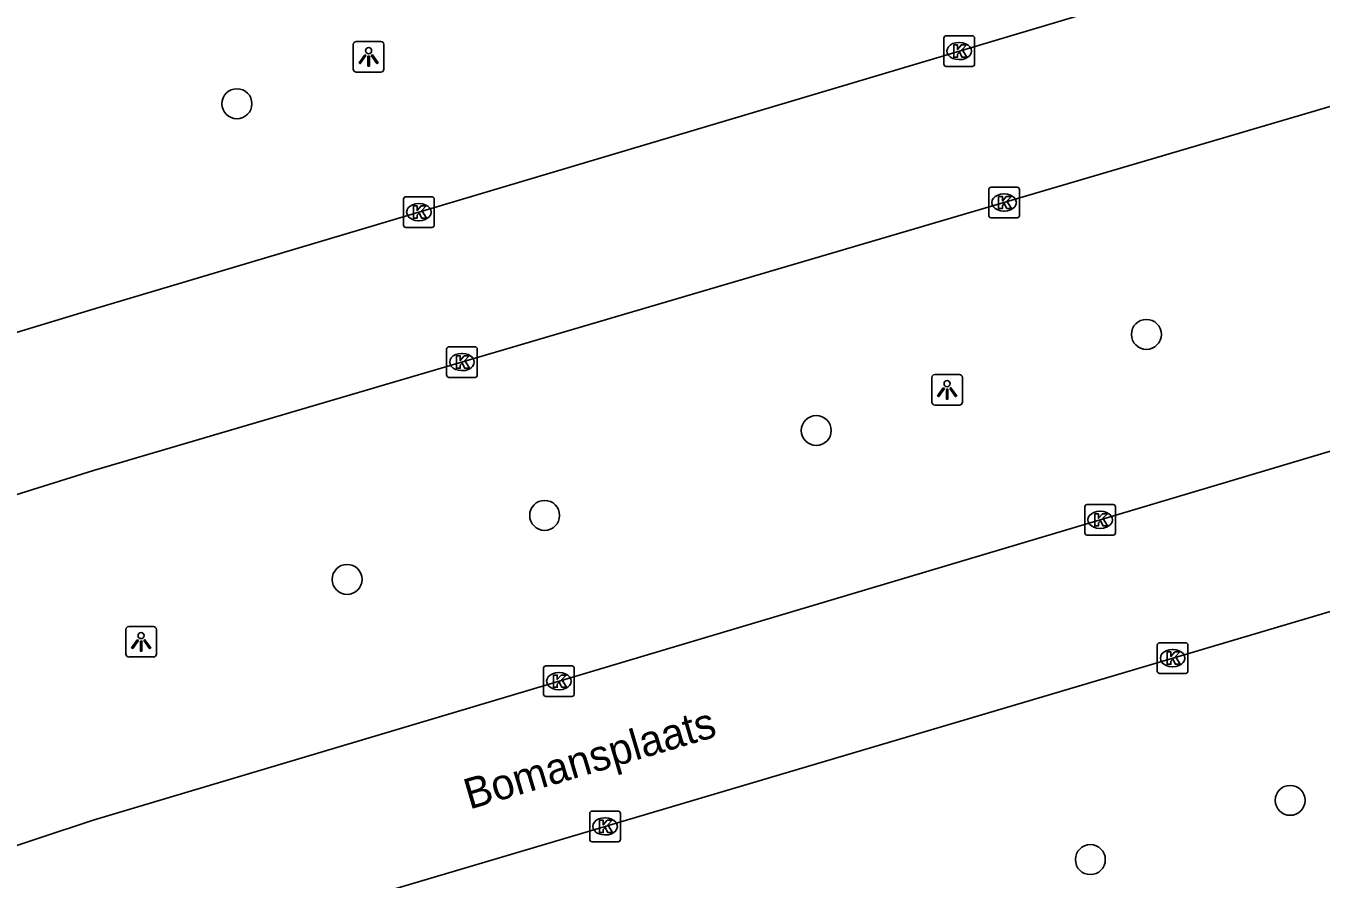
# Model space of a CAD drawing. Extents: x 161354 to 161876, y 382161 to 382804.
# Drawn here: x 161747.93 to 161790.23, y 382382.57 to 382410.43 of the extents above; entities that cross this region are included whole.
import ezdxf

# ---------------------------------------------------------------- set-up
doc = ezdxf.new("R2010")
doc.units = 0
for name, color, linetype in [('IMGEO_Boom', 7, 'Continuous'), ('IMGEO_Kolk', 7, 'Continuous'), ('IMGEO_Lichtpunt', 7, 'Continuous'), ('IMGEO_Openbare_ruimte_label', 7, 'Continuous'), ('IMGEO_Rijbaan_lokaal_open', 7, 'Continuous')]:
    doc.layers.add(name, color=color, linetype=linetype)

msp = doc.modelspace()

# ---------------------------------------------------------------- linework, layer by layer
at = {"layer": 'IMGEO_Boom'}
for centre in [(161754.825, 382407.891), (161784.522, 382400.359), (161773.743, 382397.219), (161764.873, 382394.448), (161758.423, 382392.358), (161789.216, 382385.143), (161782.692, 382383.207)]:
    msp.add_circle(centre, 0.489, dxfattribs=at)
at = {"layer": 'IMGEO_Kolk'}
for p, q in [((161777.909, 382409.184), (161777.909, 382410.036)), ((161777.984, 382410.11), (161778.836, 382410.11)), ((161778.397, 382409.89), (161778.422, 382409.89)), ((161778.91, 382410.036), (161778.91, 382409.184)), ((161778.836, 382409.11), (161777.984, 382409.11)), ((161778.42, 382409.33), (161778.395, 382409.33)), ((161779.449, 382405.164), (161780.301, 382405.164)), ((161760.266, 382403.925), (161760.266, 382404.777)), ((161760.341, 382404.851), (161761.193, 382404.851)), ((161761.267, 382404.777), (161761.267, 382403.925)), ((161779.374, 382404.238), (161779.374, 382405.09)), ((161779.862, 382404.944), (161779.887, 382404.944)), ((161780.375, 382405.09), (161780.375, 382404.238)), ((161760.754, 382404.631), (161760.779, 382404.631)), ((161779.885, 382404.384), (161779.86, 382404.384)), ((161760.777, 382404.071), (161760.752, 382404.071)), ((161780.301, 382404.164), (161779.449, 382404.164)), ((161761.193, 382403.851), (161760.341, 382403.851)), ((161761.673, 382399.029), (161761.673, 382399.881)), ((161761.748, 382399.955), (161762.6, 382399.955)), ((161762.161, 382399.735), (161762.186, 382399.735)), ((161762.674, 382399.881), (161762.674, 382399.029)), ((161762.6, 382398.955), (161761.748, 382398.955)), ((161762.184, 382399.175), (161762.159, 382399.175)), ((161782.512, 382393.877), (161782.512, 382394.729)), ((161782.587, 382394.803), (161783.439, 382394.803)), ((161783, 382394.583), (161783.025, 382394.583)), ((161783.513, 382394.729), (161783.513, 382393.877)), ((161783.439, 382393.803), (161782.587, 382393.803)), ((161783.023, 382394.023), (161782.998, 382394.023)), ((161784.878, 382389.361), (161784.878, 382390.213)), ((161784.953, 382390.287), (161785.805, 382390.287)), ((161785.366, 382390.067), (161785.391, 382390.067)), ((161785.879, 382390.213), (161785.879, 382389.361)), ((161764.914, 382389.535), (161765.766, 382389.535)), ((161785.389, 382389.507), (161785.364, 382389.507)), ((161764.839, 382388.609), (161764.839, 382389.461)), ((161765.327, 382389.315), (161765.352, 382389.315)), ((161765.84, 382389.461), (161765.84, 382388.609)), ((161785.805, 382389.287), (161784.953, 382389.287)), ((161765.35, 382388.755), (161765.325, 382388.755)), ((161765.766, 382388.535), (161764.914, 382388.535)), ((161766.345, 382383.866), (161766.345, 382384.718)), ((161766.42, 382384.792), (161767.272, 382384.792)), ((161766.833, 382384.572), (161766.858, 382384.572)), ((161767.346, 382384.718), (161767.346, 382383.866)), ((161766.856, 382384.012), (161766.831, 382384.012)), ((161767.272, 382383.792), (161766.42, 382383.792))]:
    msp.add_line(p, q, dxfattribs=at)
for points in [[(161777.909, 382409.184), (161777.909, 382410.036)], [(161777.984, 382410.11), (161778.836, 382410.11)], [(161778.23, 382409.81), (161778.353, 382409.81), (161778.353, 382409.659), (161778.483, 382409.81), (161778.647, 382409.81), (161778.501, 382409.659), (161778.654, 382409.41), (161778.502, 382409.41), (161778.417, 382409.574), (161778.353, 382409.507), (161778.353, 382409.41), (161778.23, 382409.41), (161778.23, 382409.81)], [(161778.91, 382410.036), (161778.91, 382409.184)], [(161778.836, 382409.11), (161777.984, 382409.11)], [(161779.449, 382405.164), (161780.301, 382405.164)], [(161760.266, 382403.925), (161760.266, 382404.777)], [(161760.341, 382404.851), (161761.193, 382404.851)], [(161761.267, 382404.777), (161761.267, 382403.925)], [(161779.374, 382404.238), (161779.374, 382405.09)], [(161779.695, 382404.864), (161779.818, 382404.864), (161779.818, 382404.713), (161779.948, 382404.864), (161780.112, 382404.864), (161779.966, 382404.713), (161780.119, 382404.464), (161779.967, 382404.464), (161779.882, 382404.628), (161779.818, 382404.561), (161779.818, 382404.464), (161779.695, 382404.464), (161779.695, 382404.864)], [(161780.375, 382405.09), (161780.375, 382404.238)], [(161760.587, 382404.551), (161760.71, 382404.551), (161760.71, 382404.4), (161760.84, 382404.551), (161761.004, 382404.551), (161760.858, 382404.4), (161761.011, 382404.151), (161760.859, 382404.151), (161760.774, 382404.315), (161760.71, 382404.248), (161760.71, 382404.151), (161760.587, 382404.151), (161760.587, 382404.551)], [(161780.301, 382404.164), (161779.449, 382404.164)], [(161761.193, 382403.851), (161760.341, 382403.851)], [(161761.673, 382399.029), (161761.673, 382399.881)], [(161761.748, 382399.955), (161762.6, 382399.955)], [(161761.994, 382399.655), (161762.117, 382399.655), (161762.117, 382399.504), (161762.247, 382399.655), (161762.411, 382399.655), (161762.265, 382399.504), (161762.418, 382399.255), (161762.266, 382399.255), (161762.181, 382399.419), (161762.117, 382399.352), (161762.117, 382399.255), (161761.994, 382399.255), (161761.994, 382399.655)], [(161762.674, 382399.881), (161762.674, 382399.029)], [(161762.6, 382398.955), (161761.748, 382398.955)], [(161782.512, 382393.877), (161782.512, 382394.729)], [(161782.587, 382394.803), (161783.439, 382394.803)], [(161783.513, 382394.729), (161783.513, 382393.877)], [(161782.833, 382394.503), (161782.956, 382394.503), (161782.956, 382394.352), (161783.086, 382394.503), (161783.25, 382394.503), (161783.104, 382394.352), (161783.257, 382394.103), (161783.105, 382394.103), (161783.02, 382394.267), (161782.956, 382394.2), (161782.956, 382394.103), (161782.833, 382394.103), (161782.833, 382394.503)], [(161783.439, 382393.803), (161782.587, 382393.803)], [(161784.878, 382389.361), (161784.878, 382390.213)], [(161784.953, 382390.287), (161785.805, 382390.287)], [(161785.199, 382389.987), (161785.322, 382389.987), (161785.322, 382389.836), (161785.452, 382389.987), (161785.616, 382389.987), (161785.47, 382389.836), (161785.623, 382389.587), (161785.471, 382389.587), (161785.386, 382389.751), (161785.322, 382389.684), (161785.322, 382389.587), (161785.199, 382389.587), (161785.199, 382389.987)], [(161785.879, 382390.213), (161785.879, 382389.361)], [(161764.914, 382389.535), (161765.766, 382389.535)], [(161764.839, 382388.609), (161764.839, 382389.461)], [(161765.16, 382389.235), (161765.283, 382389.235), (161765.283, 382389.084), (161765.413, 382389.235), (161765.577, 382389.235), (161765.431, 382389.084), (161765.584, 382388.835), (161765.432, 382388.835), (161765.347, 382388.999), (161765.283, 382388.932), (161765.283, 382388.835), (161765.16, 382388.835), (161765.16, 382389.235)], [(161765.84, 382389.461), (161765.84, 382388.609)], [(161785.805, 382389.287), (161784.953, 382389.287)], [(161765.766, 382388.535), (161764.914, 382388.535)], [(161766.345, 382383.866), (161766.345, 382384.718)], [(161766.42, 382384.792), (161767.272, 382384.792)], [(161766.666, 382384.492), (161766.789, 382384.492), (161766.789, 382384.341), (161766.919, 382384.492), (161767.083, 382384.492), (161766.937, 382384.341), (161767.09, 382384.092), (161766.938, 382384.092), (161766.853, 382384.256), (161766.789, 382384.189), (161766.789, 382384.092), (161766.666, 382384.092), (161766.666, 382384.492)], [(161767.346, 382384.718), (161767.346, 382383.866)], [(161767.272, 382383.792), (161766.42, 382383.792)]]:
    msp.add_lwpolyline(points, dxfattribs=at)
for centre, start, end in [((161777.986, 382410.034), 91.552, 178.448), ((161777.986, 382410.034), 91.552, 178.448), ((161778.834, 382410.034), 1.552, 88.448), ((161778.834, 382410.034), 1.552, 88.448), ((161777.986, 382409.186), 181.552, 268.448), ((161777.986, 382409.186), 181.552, 268.448), ((161778.834, 382409.186), 271.552, 358.448), ((161778.834, 382409.186), 271.552, 358.448), ((161779.451, 382405.088), 91.552, 178.448), ((161779.451, 382405.088), 91.552, 178.448), ((161780.299, 382405.088), 1.552, 88.448), ((161780.299, 382405.088), 1.552, 88.448), ((161760.343, 382404.775), 91.552, 178.448), ((161760.343, 382404.775), 91.552, 178.448), ((161761.191, 382404.775), 1.552, 88.448), ((161761.191, 382404.775), 1.552, 88.448), ((161760.343, 382403.927), 181.552, 268.448), ((161760.343, 382403.927), 181.552, 268.448), ((161761.191, 382403.927), 271.552, 358.448), ((161761.191, 382403.927), 271.552, 358.448), ((161779.451, 382404.24), 181.552, 268.448), ((161779.451, 382404.24), 181.552, 268.448), ((161780.299, 382404.24), 271.552, 358.448), ((161780.299, 382404.24), 271.552, 358.448), ((161761.75, 382399.879), 91.552, 178.448), ((161761.75, 382399.879), 91.552, 178.448), ((161762.598, 382399.879), 1.552, 88.448), ((161762.598, 382399.879), 1.552, 88.448), ((161761.75, 382399.031), 181.552, 268.448), ((161761.75, 382399.031), 181.552, 268.448), ((161762.598, 382399.031), 271.552, 358.448), ((161762.598, 382399.031), 271.552, 358.448), ((161782.589, 382394.727), 91.552, 178.448), ((161782.589, 382394.727), 91.552, 178.448), ((161783.437, 382394.727), 1.552, 88.448), ((161783.437, 382394.727), 1.552, 88.448), ((161782.589, 382393.879), 181.552, 268.448), ((161782.589, 382393.879), 181.552, 268.448), ((161783.437, 382393.879), 271.552, 358.448), ((161783.437, 382393.879), 271.552, 358.448), ((161784.955, 382390.211), 91.552, 178.448), ((161784.955, 382390.211), 91.552, 178.448), ((161785.803, 382390.211), 1.552, 88.448), ((161785.803, 382390.211), 1.552, 88.448), ((161764.916, 382389.459), 91.552, 178.448), ((161764.916, 382389.459), 91.552, 178.448), ((161765.764, 382389.459), 1.552, 88.448), ((161765.764, 382389.459), 1.552, 88.448), ((161784.955, 382389.363), 181.552, 268.448), ((161784.955, 382389.363), 181.552, 268.448), ((161785.803, 382389.363), 271.552, 358.448), ((161785.803, 382389.363), 271.552, 358.448), ((161764.916, 382388.611), 181.552, 268.448), ((161764.916, 382388.611), 181.552, 268.448), ((161765.764, 382388.611), 271.552, 358.448), ((161765.764, 382388.611), 271.552, 358.448), ((161766.422, 382384.716), 91.552, 178.448), ((161766.422, 382384.716), 91.552, 178.448), ((161767.27, 382384.716), 1.552, 88.448), ((161767.27, 382384.716), 1.552, 88.448), ((161766.422, 382383.868), 181.552, 268.448), ((161766.422, 382383.868), 181.552, 268.448), ((161767.27, 382383.868), 271.552, 358.448), ((161767.27, 382383.868), 271.552, 358.448)]:
    msp.add_arc(centre, 0.0765, start, end, dxfattribs=at)
for centre, major_axis, ratio, start_param, end_param in [((161778.396, 382409.61), (-0.387, 0.002), 0.722429, 4.712389, 7.853982), ((161778.421, 382409.61), (-0.39, 0.002), 0.717154, 1.570796, 4.712389), ((161779.861, 382404.664), (-0.387, 0.002), 0.722429, 4.712389, 7.853982), ((161779.886, 382404.664), (-0.39, 0.002), 0.717154, 1.570796, 4.712389), ((161760.753, 382404.351), (-0.387, 0.002), 0.722429, 4.712389, 7.853982), ((161760.778, 382404.351), (-0.39, 0.002), 0.717154, 1.570796, 4.712389), ((161762.16, 382399.455), (-0.387, 0.002), 0.722429, 4.712389, 7.853982), ((161762.185, 382399.455), (-0.39, 0.002), 0.717154, 1.570796, 4.712389), ((161782.999, 382394.303), (-0.387, 0.002), 0.722429, 4.712389, 7.853982), ((161783.024, 382394.303), (-0.39, 0.002), 0.717154, 1.570796, 4.712389), ((161785.365, 382389.787), (-0.387, 0.002), 0.722429, 4.712389, 7.853982), ((161785.39, 382389.787), (-0.39, 0.002), 0.717154, 1.570796, 4.712389), ((161765.326, 382389.035), (-0.387, 0.002), 0.722429, 4.712389, 7.853982), ((161765.351, 382389.035), (-0.39, 0.002), 0.717154, 1.570796, 4.712389), ((161766.832, 382384.292), (-0.387, 0.002), 0.722429, 4.712389, 7.853982), ((161766.857, 382384.292), (-0.39, 0.002), 0.717154, 1.570796, 4.712389)]:
    msp.add_ellipse(centre, major_axis=major_axis, ratio=ratio, start_param=start_param, end_param=end_param, dxfattribs=at)
at = {"layer": 'IMGEO_Lichtpunt'}
for p, q in [((161758.626, 382409.826), (161758.626, 382409.019)), ((161758.626, 382409.826), (161758.626, 382409.019)), ((161759.528, 382409.921), (161758.72, 382409.921)), ((161759.528, 382409.921), (161758.72, 382409.921)), ((161759.622, 382409.019), (161759.622, 382409.826)), ((161759.622, 382409.019), (161759.622, 382409.826)), ((161758.72, 382408.925), (161759.528, 382408.925)), ((161758.72, 382408.925), (161759.528, 382408.925)), ((161777.516, 382398.952), (161777.516, 382398.145)), ((161777.516, 382398.952), (161777.516, 382398.145)), ((161778.418, 382399.047), (161777.61, 382399.047)), ((161778.418, 382399.047), (161777.61, 382399.047)), ((161778.512, 382398.145), (161778.512, 382398.952)), ((161778.512, 382398.145), (161778.512, 382398.952)), ((161777.61, 382398.051), (161778.418, 382398.051)), ((161777.61, 382398.051), (161778.418, 382398.051)), ((161752.1, 382390.82), (161751.292, 382390.82)), ((161752.1, 382390.82), (161751.292, 382390.82)), ((161751.198, 382390.725), (161751.198, 382389.918)), ((161751.198, 382390.725), (161751.198, 382389.918)), ((161752.194, 382389.918), (161752.194, 382390.725)), ((161752.194, 382389.918), (161752.194, 382390.725)), ((161751.292, 382389.824), (161752.1, 382389.824)), ((161751.292, 382389.824), (161752.1, 382389.824))]:
    msp.add_line(p, q, dxfattribs=at)
for points in [[(161759, 382409.49), (161759.039, 382409.462), (161758.851, 382409.2), (161758.813, 382409.227), (161759, 382409.49)], [(161759.102, 382409.442), (161759.149, 382409.442), (161759.149, 382409.12), (161759.102, 382409.12), (161759.102, 382409.442)], [(161759.212, 382409.462), (161759.25, 382409.489), (161759.437, 382409.227), (161759.398, 382409.199), (161759.212, 382409.462)], [(161777.89, 382398.616), (161777.929, 382398.588), (161777.741, 382398.326), (161777.703, 382398.353), (161777.89, 382398.616)], [(161777.992, 382398.568), (161778.039, 382398.568), (161778.039, 382398.246), (161777.992, 382398.246), (161777.992, 382398.568)], [(161778.102, 382398.588), (161778.14, 382398.615), (161778.327, 382398.353), (161778.288, 382398.325), (161778.102, 382398.588)], [(161751.572, 382390.389), (161751.611, 382390.361), (161751.423, 382390.099), (161751.385, 382390.126), (161751.572, 382390.389)], [(161751.674, 382390.341), (161751.721, 382390.341), (161751.721, 382390.019), (161751.674, 382390.019), (161751.674, 382390.341)], [(161751.784, 382390.361), (161751.822, 382390.388), (161752.009, 382390.126), (161751.97, 382390.098), (161751.784, 382390.361)]]:
    msp.add_lwpolyline(points, dxfattribs=at)
for centre in [(161759.125, 382409.624), (161778.015, 382398.75), (161751.697, 382390.523)]:
    msp.add_circle(centre, 0.0994, dxfattribs=at)
for centre, start, end in [((161758.72, 382409.826), 90, 180), ((161758.72, 382409.826), 90, 180), ((161759.528, 382409.826), 0, 90), ((161759.528, 382409.826), 0, 90), ((161758.72, 382409.019), 180, 270), ((161758.72, 382409.019), 180, 270), ((161759.528, 382409.019), 270, 0), ((161759.528, 382409.019), 270, 360), ((161777.61, 382398.952), 90, 180), ((161777.61, 382398.952), 90, 180), ((161778.418, 382398.952), 0, 90), ((161778.418, 382398.952), 0, 90), ((161777.61, 382398.145), 180, 270), ((161777.61, 382398.145), 180, 270), ((161778.418, 382398.145), 270, 0), ((161778.418, 382398.145), 270, 360), ((161751.292, 382390.725), 90, 180), ((161751.292, 382390.725), 90, 180), ((161752.1, 382390.725), 0, 90), ((161752.1, 382390.725), 0, 90), ((161751.292, 382389.918), 180, 270), ((161751.292, 382389.918), 180, 270), ((161752.1, 382389.918), 270, 0), ((161752.1, 382389.918), 270, 360)]:
    msp.add_arc(centre, 0.0946, start, end, dxfattribs=at)
at = {"layer": 'IMGEO_Rijbaan_lokaal_open'}
for points in [[(161762.37, 382416.247), (161750.097, 382412.597), (161738.436, 382409.04), (161741.615, 382398.598), (161750.1, 382401.17), (161789.929, 382413.043), (161786.633, 382423.61), (161771.29, 382418.743)], [(161750.141, 382395.914), (161791.477, 382408.079), (161794.688, 382397.782), (161750.131, 382384.5), (161746.473, 382383.289), (161743.218, 382393.745), (161750.141, 382395.914)], [(161799.315, 382382.951), (161796.182, 382392.991), (161750.032, 382379.308), (161747.962, 382378.639), (161749.867, 382372.389), (161751.126, 382368.268), (161799.315, 382382.951)]]:
    msp.add_lwpolyline(points, dxfattribs=at)

# ---------------------------------------------------------------- texts
at = {"layer": 'IMGEO_Openbare_ruimte_label'}
msp.add_text('Bomansplaats', height=1, rotation=16.4962, dxfattribs=at).set_placement((161762.418, 382384.838))

doc.saveas('drawing.dxf')
